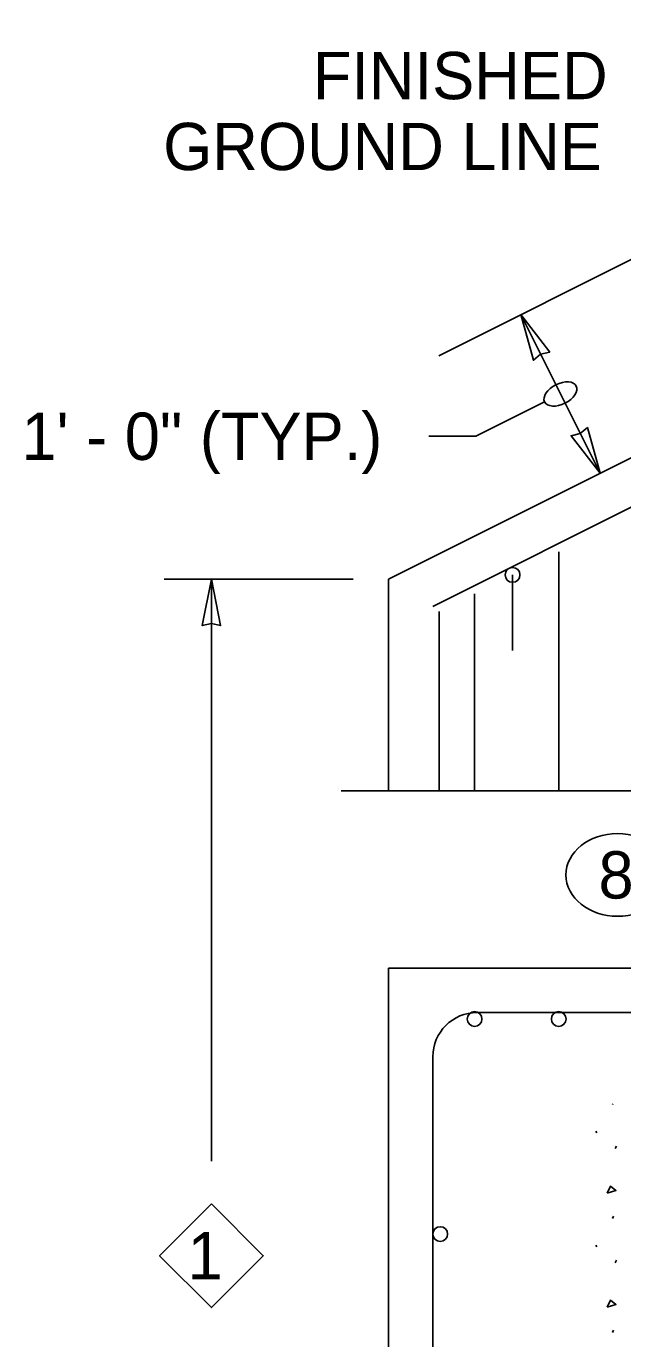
# Model space of a CAD drawing. Extents: x 99862 to 103151, y 100000 to 102076.
# Drawn here: x 102259.4 to 102461.5, y 100751.6 to 101195.7 of the extents above; entities that cross this region are included whole.
import ezdxf

# ---------------------------------------------------------------- set-up
doc = ezdxf.new("R2010")
doc.units = 0
for name, color, linetype in [('Level 10', 7, 'Continuous'), ('Level 15', 7, 'Continuous'), ('Level 2', 7, 'Continuous'), ('Level 20', 7, 'Continuous'), ('Level 23', 7, 'Continuous'), ('Level 5', 7, 'Continuous')]:
    doc.layers.add(name, color=color, linetype=linetype)

msp = doc.modelspace()

# ---------------------------------------------------------------- linework, layer by layer
at = {"layer": 'Level 10'}
for p, q in [((102397.17, 100999.36), (102789.88, 101195.71)), ((102397.17, 100999.36), (102789.88, 101195.71)), ((102439.82, 100936.99), (102439.82, 101017.89)), ((102424.17, 101010.07), (102424.17, 100984.42)), ((102424.17, 101010.07), (102424.17, 100984.42)), ((102411.32, 100936.99), (102411.32, 101003.64)), ((102399.36, 100997.66), (102399.36, 100936.99)), ((102412.17, 100861.99), (102737.17, 100861.99)), ((102397.17, 100726.99), (102397.17, 100846.99))]:
    msp.add_line(p, q, dxfattribs=at)
for centre in [(102424.17, 101010.07), (102424.17, 101010.07), (102411.32, 100859.77), (102411.32, 100859.77), (102439.82, 100859.77), (102439.82, 100859.77), (102399.67, 100786.99), (102399.67, 100786.99)]:
    msp.add_circle(centre, 2.5, dxfattribs=at)
msp.add_arc((102412.17, 100846.99), 15, 90, 180, dxfattribs=at)
msp.add_arc((102412.17, 100846.99), 15, 90, 180, dxfattribs=at)
at = {"layer": 'Level 15'}
for p, q in [((102426.98, 101098.12), (102453.81, 101044.45)), ((102426.98, 101098.12), (102453.81, 101044.45)), ((102411.77, 101056.97), (102435.03, 101068.6)), ((102411.77, 101056.97), (102435.03, 101068.6)), ((102411.77, 101056.97), (102395.77, 101056.97)), ((102411.77, 101056.97), (102395.77, 101056.97)), ((102370.17, 101008.63), (102306.17, 101008.63)), ((102370.17, 101008.63), (102306.17, 101008.63)), ((102322.17, 100811.67), (102322.17, 101008.63)), ((102366.17, 100936.99), (102567.55, 100936.99)), ((102366.17, 100936.99), (102567.55, 100936.99))]:
    msp.add_line(p, q, dxfattribs=at)
for points in [[(102426.98, 101098.12), (102431.25, 101082.67), (102433.68, 101084.7), (102436.77, 101085.43)], [(102426.98, 101098.12), (102431.25, 101082.67), (102433.68, 101084.7), (102436.77, 101085.43)], [(102453.81, 101044.45), (102444.02, 101057.14), (102447.1, 101057.86), (102449.53, 101059.9)], [(102453.81, 101044.45), (102444.02, 101057.14), (102447.1, 101057.86), (102449.53, 101059.9)], [(102322.17, 101008.63), (102325.26, 100992.91), (102322.17, 100993.64), (102319.09, 100992.91)]]:
    msp.add_lwpolyline(points, close=True, dxfattribs=at)
msp.add_ellipse((102440.39, 101071.28), major_axis=(5.37, 2.68), ratio=0.57735, dxfattribs=at)
msp.add_ellipse((102440.39, 101071.28), major_axis=(5.37, 2.68), ratio=0.57735, dxfattribs=at)
at = {"layer": 'Level 2'}
for p, q in [((102382.17, 101008.63), (102592.17, 101113.63)), ((102382.17, 101008.63), (102592.17, 101113.63)), ((102382.17, 100936.99), (102382.17, 101008.63)), ((102382.17, 100936.99), (102382.17, 101008.63)), ((102382.17, 100696.99), (102382.17, 100876.99)), ((102382.17, 100876.99), (102982.17, 100876.99)), ((102382.17, 100696.99), (102382.17, 100876.99)), ((102382.17, 100876.99), (102982.17, 100876.99))]:
    msp.add_line(p, q, dxfattribs=at)
at = {"layer": 'Level 20'}
msp.add_lwpolyline([(102322.17, 100797.23), (102339.73, 100779.67), (102322.17, 100762.12), (102304.62, 100779.67)], close=True, dxfattribs=at)
msp.add_ellipse((102459.76, 100908.54), major_axis=(-17.5, 0), ratio=0.8, dxfattribs=at)
at = {"layer": 'Level 23'}
for p, q in [((102458.04, 100830.82), (102458.14, 100831.03)), ((102458.04, 100830.82), (102458.14, 100831.03)), ((102452.34, 100821.82), (102452.71, 100821.27)), ((102452.34, 100821.82), (102452.71, 100821.27)), ((102458.97, 100815.91), (102459.35, 100816.75)), ((102458.97, 100815.91), (102459.35, 100816.75)), ((102458.04, 100792.23), (102458.42, 100793.07)), ((102458.04, 100792.23), (102458.42, 100793.07)), ((102452.34, 100783.24), (102452.71, 100782.68)), ((102452.34, 100783.24), (102452.71, 100782.68)), ((102458.97, 100777.32), (102459.35, 100778.16)), ((102458.97, 100777.32), (102459.35, 100778.16)), ((102458.04, 100753.64), (102458.42, 100754.48)), ((102458.04, 100753.64), (102458.42, 100754.48))]:
    msp.add_line(p, q, dxfattribs=at)
for points in [[(102456.2, 100800.85), (102457.32, 100803.18), (102459.18, 100801.78), (102456.2, 100800.85)], [(102456.2, 100800.85), (102457.32, 100803.18), (102459.18, 100801.78), (102456.2, 100800.85)], [(102456.2, 100762.26), (102457.32, 100764.59), (102459.18, 100763.2), (102456.2, 100762.26)], [(102456.2, 100762.26), (102457.32, 100764.59), (102459.18, 100763.2), (102456.2, 100762.26)]]:
    msp.add_lwpolyline(points, dxfattribs=at)
at = {"layer": 'Level 5'}
msp.add_line((102399.23, 101084.24), (102592.17, 101180.71), dxfattribs=at)
msp.add_line((102399.23, 101084.24), (102592.17, 101180.71), dxfattribs=at)

# ---------------------------------------------------------------- texts
at = {"layer": 'Level 20'}
for s, p in [('FINISHED', (102356.53, 101171.03)), ('GROUND LINE', (102305.83, 101147.03)), ('8', (102453.29, 100900.54)), ('1', (102314.1, 100771.67))]:
    msp.add_text(s, height=16, dxfattribs=at).set_placement(p)
msp.add_text('1\' - 0" (TYP.)', height=16, rotation=360, dxfattribs=at).set_placement((102257.82, 101048.97))

doc.saveas('drawing.dxf')
